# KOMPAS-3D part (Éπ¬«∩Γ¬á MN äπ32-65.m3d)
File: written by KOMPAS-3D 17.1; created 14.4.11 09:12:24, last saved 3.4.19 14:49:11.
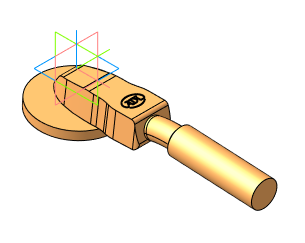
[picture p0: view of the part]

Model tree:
1. Плоскость XY
2. Плоскость ZX
3. Плоскость ZY
4. Ось X
5. Ось Y
6. Ось Z
7. Начало координат
8. Операция без истории:4  (with: Сечение модели:1)

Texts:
  Точка начала. Х
  Точка начала. Y
  Точка начала. Z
